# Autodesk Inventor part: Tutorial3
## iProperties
Shininess: 64.0
Length Units: 11269
Angle Units: 11279
Time Units: 11290
Mass Units: 11283
Length Display Precision: 3
Angle Display Precision: 2
Compacted: True
Part Number: Tutorial3
Document SubType Name: Modeling
Created: 2002-11
Designer: deepak
Density: 1 g/cm^3
Density: 0.0
Volumn: 0.0
Area: 0.0
PropertySet Name: Model Information
Control State: 0
Master: False
Checked Out: False
Author: deepak
